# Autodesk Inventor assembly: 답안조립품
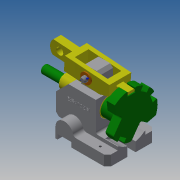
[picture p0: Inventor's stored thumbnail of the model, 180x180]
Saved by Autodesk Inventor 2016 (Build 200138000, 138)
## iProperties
Created: 2016-11
Part Number: 답안조립품
Document SubType Name: Assembly
Designer: Administrator
Author: Administrator
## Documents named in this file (8)
- D:\461107V1004\답안조립품.iam
- D:\461107V1004\본체.ipt
- D:\461107V1004\부시.ipt
- D:\461107V1004\분할축.ipt
- D:\461107V1004\분할대.ipt
- D:\461107V1004\클레비스핀.ipt
- D:\461107V1004\와셔.ipt
- D:\461107V1004\원통형핀.ipt
